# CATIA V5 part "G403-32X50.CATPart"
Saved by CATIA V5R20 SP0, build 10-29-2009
Part number: G403-32X50
Definition: NONE
Nomenclature: G403-32X50
Source: Unknown
Description: G403-32X50
Bounding box of the stored display mesh (mm): x -25 to 25, y -22.5 to 22.5, z -22.5 to 22.5
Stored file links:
  C:\Users\Utente\Desktop\IO LAVORO\3D X SITO CF\X SITO\PLASTICA\G403\G403-32X50.CATPart
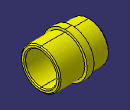
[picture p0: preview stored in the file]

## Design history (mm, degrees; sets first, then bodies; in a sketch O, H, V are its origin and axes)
Body1 "G403-32X50" (main body)
  Solid1: solid without history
